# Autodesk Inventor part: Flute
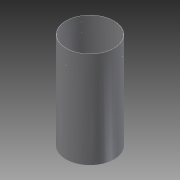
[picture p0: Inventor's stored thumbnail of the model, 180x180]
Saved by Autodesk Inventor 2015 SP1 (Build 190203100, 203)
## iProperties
Created: 2013-06
Part Number: Flute
Material: Steel, Mild
Document SubType Name: Sheet Metal
Designer: 1103005
Density: 7.86 g/cm^3
Sheet Metal Rule: Default_mm
Appearance: Steel
Flat Pattern Width: 30 cm
Flat Pattern Length: 46.6026 cm
Flat Pattern Area: 1398.08 cm^2
Sheet Metal Width: 300.000 mm
Sheet Metal Length: 466.026 mm
Sheet Metal Area: 139807.665 mm^2
Author: 1103005
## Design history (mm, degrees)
node "Contour Flange1"
  sketch "Sketch1"
    geometry: A1 r 75 centre (0, 0) between (-0.5, 74.998) and (0.5, 74.998); 1 further point
    constraints: 2 point on circle, 1 centre point, 1 coincident
    dimensions: "d0" = 150 diameter of A1
workplane "Work Plane1"
sketch "Sketch3"
  geometry: L1 (75, 150)-(-75, 150) reference; 5 further points
  constraints: 1 midpoint, 1 vertical alignment
  dimensions: "d24" = 15 vertical distance of point (0.5, 150) point (0, 135)
hole "Hole2" sketch "Sketch3" at (0, 135) diameter "d25" = 3.5; stored, may be unused: countersink angle "d29" = 90 deg, drill point angle "d31" = 118 deg; dims "d26" = 6, "d27" = 4, "d28" = 2, "d30" = 1.2 (= Thickness)
pattern_circular "Circular Pattern2" dims angle "d33" = 360 deg
pattern_linear "Rectangular Pattern1"
body "Solid1"
face "Plate1" dims "d3" = 1.2 (= BendReliefWidth), "d4" = 0.6 (= BendReliefDepth), "d5" = 2.4 (= MinimumRemnant), "d6" = 1.2 (= BendRadius), "d7" = 300, "d8" = 1.2 (= BendRadius), "d9" = 1.5, "d10" = 4.8 (= CornerReliefSize), "d11" = 1.2 (= GapSize), "d12" = 1.2 (= JacobiRadiusSize), "SeamGap" = 0.01, "Thickness" = 1.2
bend "Bend1" dims "d3" = 1.2 (= BendReliefWidth), "d4" = 0.6 (= BendReliefDepth), "d5" = 2.4 (= MinimumRemnant), "d6" = 1.2 (= BendRadius), "d8" = 1.2 (= BendRadius), "d9" = 1.5, "SeamGap" = 0.01, "Thickness" = 1.2
feature "Corner1" dims "d9" = 1.5, "d10" = 4.8 (= CornerReliefSize), "d11" = 1.2 (= GapSize), "d12" = 1.2 (= JacobiRadiusSize)
feature "Definition1"
other parameters: "BendRadius" = 1.2 (= Thickness), "BendReliefWidth" = 1.2 (= Thickness), "BendReliefDepth" = 0.6 (= 0.5 x Thickness), "CornerReliefSize" = 4.8 (= 4 x Thickness), "MinimumRemnant" = 2.4 (= 2 x Thickness), "TransitionRadius" = 1.2 (= BendRadius), "JacobiRadiusSize" = 1.2 (= BendRadius), "GapSize" = 1.2 (= Thickness), "BendRadius" = 1.2, "BendReliefDepth" = 0.6, "BendReliefWidth" = 1.2, "CornerReliefSize" = 4.8, "GapSize" = 1.2, "JacobiRadiusSize" = 1.2, "MinimumRemnant" = 2.4, "Thickness" = 1.2, "TransitionRadius" = 1.2
